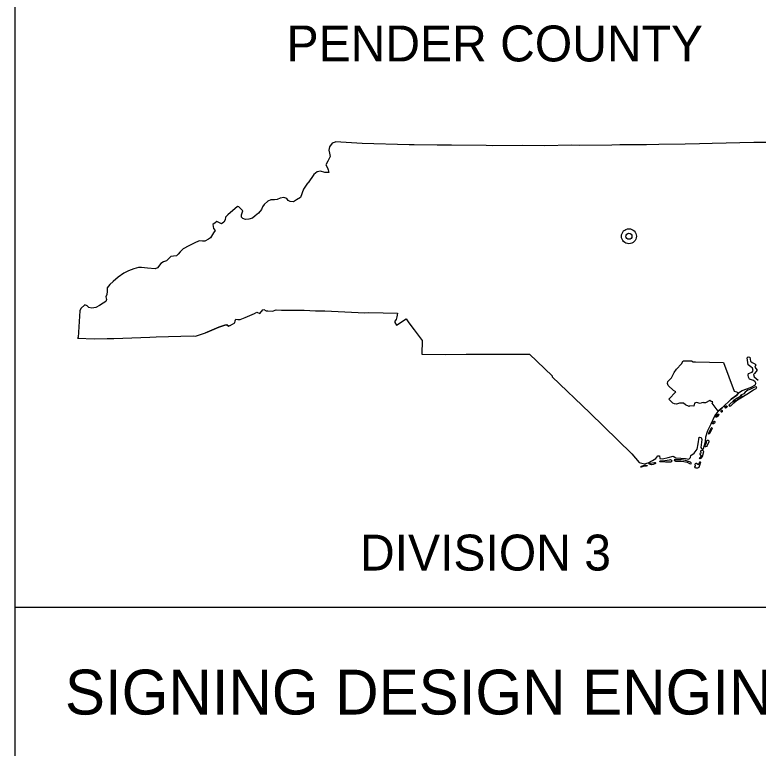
# Model space of a CAD drawing. Extents: x 0 to 1700, y -103 to 1100.
# Drawn here: x 1586.5 to 1660.9, y 952.5 to 1026 of the extents above; entities that cross this region are included whole.
import ezdxf

# ---------------------------------------------------------------- set-up
doc = ezdxf.new("R2010")
doc.units = 0
doc.layers.add('Level 35', color=7, linetype='Continuous')
doc.layers.add('Sheet_Plan_CELL', color=7, linetype='Continuous')

msp = doc.modelspace()

# ---------------------------------------------------------------- linework, layer by layer
at = {"layer": 'Level 35'}
for points in [[(1656.389, 987.241), (1656.214, 987.258), (1656.098, 987.373), (1655.658, 987.124), (1655.494, 987.126), (1655.408, 987.181), (1655.28, 987.149), (1655.129, 987.067), (1654.738, 987.174), (1654.563, 987.11), (1654.494, 986.798), (1654.079, 986.842), (1654.023, 986.757), (1653.657, 986.927), (1653.441, 987.098), (1653.034, 987.113), (1652.743, 987.014), (1652.544, 987.047), (1652.374, 987.09), (1651.982, 987.506), (1652.682, 988.238), (1652.434, 988.388), (1651.902, 988.869), (1651.843, 989.081), (1651.892, 989.289), (1652.242, 989.649), (1652.526, 990.183), (1652.734, 990.513), (1653.238, 991.05), (1653.426, 991.343), (1653.882, 991.36), (1654.238, 991.354), (1654.426, 991.254), (1654.657, 991.242), (1657.46, 991.179), (1658.52, 988.302), (1658.744, 988.249), (1658.971, 988.142), (1658.804, 987.901), (1658.237, 987.487), (1657.322, 986.648), (1656.93, 986.285), (1656.308, 987.093)], [(1659.182, 987.639), (1658.764, 987.382), (1658.503, 987.129), (1658.194, 986.84), (1658.048, 986.803), (1658.012, 986.853), (1658.026, 986.929), (1658.104, 987.013), (1658.425, 987.319), (1658.627, 987.471), (1658.649, 987.504), (1658.722, 987.578), (1658.837, 987.589), (1659.125, 987.787), (1659.209, 987.912), (1659.391, 987.76)], [(1657.603, 986.745), (1657.724, 986.824), (1657.763, 986.829), (1657.813, 986.778), (1657.821, 986.746), (1657.806, 986.698), (1657.77, 986.654), (1657.734, 986.627), (1657.704, 986.618), (1657.67, 986.614), (1657.632, 986.649), (1657.595, 986.698)], [(1657.343, 986.276), (1657.24, 986.221), (1657.201, 986.286), (1657.256, 986.346)]]:
    msp.add_lwpolyline(points, close=True, dxfattribs=at)
for radius in [0.752, 0.3]:
    msp.add_circle((1647.98, 1003.838), radius, dxfattribs=at)
at = {"layer": 'Sheet_Plan_CELL'}
for p, q in [((1586.453, 88.909), (1586.477, 1077.498)), ((1686.502, 966.628), (1586.504, 966.628))]:
    msp.add_line(p, q, dxfattribs=at)
for points in [[(1662.247, 1013.235), (1660.486, 1013.229), (1656.334, 1013.137), (1655.047, 1013.095), (1653.608, 1013.064), (1650.976, 1013.035), (1649.738, 1013.02), (1647.069, 1013.014), (1646.275, 1012.963), (1643.073, 1012.95), (1642.194, 1012.977), (1639.549, 1012.92), (1637.367, 1012.95), (1634.293, 1012.914), (1633.669, 1012.952), (1630.197, 1012.962), (1628.76, 1012.988), (1626.454, 1013.011), (1625.948, 1012.999), (1621.267, 1013.13), (1618.564, 1013.309), (1618.532, 1013.273), (1618.237, 1013.16), (1617.995, 1012.82), (1617.908, 1012.488), (1617.99, 1012.161), (1618.044, 1011.838), (1617.814, 1011.373), (1617.626, 1011.014), (1617.766, 1010.707), (1617.848, 1010.49), (1617.91, 1010.222), (1617.495, 1010.248), (1617.078, 1010.358), (1616.749, 1010.29), (1616.406, 1010.019), (1615.838, 1009.202), (1615.79, 1009.153), (1615.38, 1008.576), (1615.058, 1007.714), (1614.681, 1007.488), (1614.378, 1007.295), (1614.048, 1007.323), (1613.852, 1007.416), (1613.711, 1007.611), (1613.406, 1007.718), (1613.023, 1007.657), (1612.729, 1007.53), (1612.476, 1007.506), (1612.1, 1007.499), (1611.789, 1007.346), (1611.427, 1007.008), (1611.275, 1006.795), (1611.169, 1006.507), (1610.862, 1006.163), (1610.522, 1005.891), (1610.258, 1005.664), (1609.885, 1005.56), (1609.563, 1005.531), (1609.297, 1005.618), (1609.163, 1005.77), (1609.165, 1006.002), (1609.283, 1006.397), (1608.903, 1006.798), (1608.767, 1006.814), (1607.79, 1005.977), (1607.567, 1005.744), (1607.534, 1005.475), (1607.395, 1005.247), (1607.154, 1005.084), (1606.698, 1005.316), (1606.53, 1005.186), (1606.287, 1005.01), (1606.349, 1004.608), (1606.507, 1004.426), (1606.351, 1004.172), (1606.042, 1003.678), (1605.846, 1003.537)], [(1605.846, 1003.537), (1605.504, 1003.333), (1605.269, 1003.333), (1604.928, 1003.373), (1604.405, 1003.148), (1603.876, 1002.883), (1603.301, 1002.569), (1603.003, 1002.264), (1602.811, 1002.041), (1602.639, 1001.871), (1602.332, 1001.838), (1602.081, 1001.812), (1601.878, 1001.604), (1601.66, 1001.385), (1601.33, 1001.273), (1601.089, 1001.096), (1600.751, 1000.673), (1600.505, 1000.565), (1599.741, 1000.623), (1599.143, 1000.69), (1598.828, 1000.697), (1598.361, 1000.586), (1597.844, 1000.385), (1597.364, 1000.153), (1596.808, 999.725), (1596.307, 999.292), (1595.958, 998.991), (1595.701, 998.654), (1595.716, 998.287), (1595.685, 998.006), (1595.562, 997.763), (1595.641, 997.484), (1595.565, 997.29), (1595.302, 997.142), (1594.945, 996.883), (1594.582, 996.692), (1594.165, 996.628), (1593.856, 996.687), (1593.712, 996.878), (1593.474, 996.957), (1593.054, 996.609), (1592.974, 996.375), (1592.785, 993.7), (1592.723, 993.626), (1594.421, 993.556), (1595.706, 993.581), (1596.376, 993.59), (1599.967, 993.722), (1600.626, 993.757), (1604.313, 993.862), (1604.539, 993.808), (1605.565, 994.16), (1605.711, 994.237), (1606.892, 994.732), (1607.49, 994.917), (1607.698, 994.946), (1607.847, 994.82), (1608.034, 994.892), (1608.493, 995.174), (1608.543, 995.357), (1608.578, 995.529), (1608.78, 995.504), (1609.025, 995.488), (1609.545, 995.708), (1610.469, 996.082), (1610.692, 996.217), (1610.992, 996.099), (1611.286, 996.468), (1611.414, 996.506), (1611.63, 996.371), (1611.792, 996.351), (1612.268, 996.319), (1612.641, 996.448), (1613.161, 996.437), (1615.449, 996.418), (1616.581, 996.367), (1617.526, 996.353), (1621.51, 996.177), (1621.911, 996.204), (1624.797, 996.121), (1624.732, 995.765), (1624.654, 995.505), (1624.52, 995.334), (1624.527, 995.184), (1624.695, 994.918), (1625.648, 995.543), (1625.922, 995.153), (1626.453, 994.457), (1627.268, 993.37), (1627.225, 992.026), (1629.572, 991.99), (1631.683, 992.022), (1635.705, 992.008), (1637.857, 992.021), (1638.02, 992.009), (1640.276, 989.84), (1640.29, 989.757), (1644.059, 986.135), (1648.258, 982.019), (1649.019, 981.143)], [(1608.034, 994.892), (1607.847, 994.82), (1607.698, 994.946), (1607.49, 994.917), (1606.892, 994.732), (1605.711, 994.237), (1605.565, 994.16)], [(1649.019, 981.143), (1649.542, 981.03), (1649.899, 981.132), (1650.33, 981.355), (1650.662, 981.555), (1650.869, 981.815), (1651.045, 981.813), (1651.084, 981.565), (1651.346, 981.508), (1651.925, 981.639), (1652.409, 981.772), (1652.682, 981.619), (1653.189, 981.573), (1653.662, 981.56), (1653.989, 981.491), (1654.166, 981.649), (1654.2, 981.844), (1654.527, 982.084), (1654.818, 982.504), (1654.934, 983.008), (1655.003, 983.709), (1655.042, 983.702), (1655.212, 983.659), (1655.27, 983.448), (1655.2, 982.667), (1655.243, 982.565), (1655.331, 982.502), (1655.42, 982.503), (1655.459, 982.559), (1655.51, 982.802), (1655.641, 983.236), (1655.671, 983.715), (1655.878, 984.352), (1656.214, 985.021), (1656.601, 985.816), (1656.843, 986.179), (1656.93, 986.285), (1657.322, 986.648), (1658.237, 987.487), (1658.804, 987.901), (1658.971, 988.142), (1659.328, 988.377), (1660.149, 988.678), (1660.662, 988.939), (1660.707, 989.107), (1660.638, 989.254), (1660.453, 989.368), (1660.053, 989.506), (1659.951, 989.7), (1659.933, 989.906), (1659.978, 990.074), (1660.317, 990.204), (1660.414, 990.363), (1660.375, 990.6), (1660.181, 990.743), (1660.06, 990.832), (1659.933, 990.962), (1659.821, 991.633), (1659.925, 991.75), (1660.085, 991.722), (1660.177, 991.326), (1660.313, 991.166), (1660.61, 991.06), (1660.684, 990.938), (1660.585, 990.698), (1660.845, 990.395), (1660.568, 990.078), (1660.465, 989.961), (1660.537, 989.759), (1660.939, 989.403)], [(1658.425, 987.319), (1658.104, 987.013), (1658.026, 986.929), (1658.012, 986.853), (1658.048, 986.803), (1658.194, 986.84), (1658.503, 987.129), (1658.764, 987.382), (1659.182, 987.639), (1659.81, 988.002), (1660.452, 988.441), (1660.678, 988.533), (1660.735, 988.589), (1660.789, 988.708), (1660.668, 988.754), (1660.5, 988.664), (1660.084, 988.487), (1659.896, 988.404), (1659.636, 988.204), (1659.497, 988.051), (1659.209, 987.912), (1659.125, 987.787), (1658.837, 987.589), (1658.722, 987.578), (1658.649, 987.504), (1658.627, 987.471), (1658.439, 987.329)], [(1657.603, 986.745), (1657.724, 986.824), (1657.763, 986.829), (1657.786, 986.812), (1657.813, 986.778), (1657.821, 986.746), (1657.806, 986.698), (1657.77, 986.654), (1657.734, 986.627), (1657.704, 986.618), (1657.67, 986.614), (1657.632, 986.649), (1657.595, 986.698), (1657.589, 986.725), (1657.603, 986.745)], [(1657.256, 986.346), (1657.201, 986.286), (1657.196, 986.253), (1657.211, 986.227), (1657.24, 986.221), (1657.287, 986.234), (1657.343, 986.276), (1657.364, 986.302), (1657.357, 986.326), (1657.31, 986.368), (1657.294, 986.374), (1657.272, 986.365), (1657.26, 986.351)], [(1656.718, 985.751), (1656.792, 985.875), (1656.87, 985.959), (1656.917, 985.994), (1656.953, 985.997), (1656.983, 985.97), (1657.001, 985.932), (1656.962, 985.888), (1656.895, 985.798), (1656.836, 985.738), (1656.747, 985.691), (1656.721, 985.69), (1656.703, 985.703), (1656.695, 985.718), (1656.718, 985.751)], [(1655.958, 984.106), (1655.949, 984.019), (1655.964, 984.011), (1655.999, 984.017), (1656.049, 984.045), (1656.079, 984.083), (1656.336, 984.515), (1656.345, 984.572), (1656.335, 984.602), (1656.297, 984.628), (1656.26, 984.628), (1656.206, 984.597), (1656.174, 984.557), (1655.975, 984.167), (1655.957, 984.107)], [(1656.353, 985.052), (1656.394, 985.142), (1656.446, 985.217), (1656.495, 985.257), (1656.554, 985.288), (1656.588, 985.279), (1656.601, 985.248), (1656.579, 985.178), (1656.541, 985.093), (1656.5, 985.053), (1656.445, 985.017), (1656.373, 985.024), (1656.355, 985.032), (1656.351, 985.059)], [(1655.749, 983.114), (1655.755, 983.237), (1655.764, 983.328), (1655.806, 983.374), (1655.866, 983.4), (1655.925, 983.383), (1655.983, 983.338), (1655.982, 983.225), (1655.828, 982.86), (1655.741, 982.755), (1655.663, 982.717), (1655.615, 982.739), (1655.609, 982.799), (1655.67, 982.931), (1655.751, 983.121)], [(1655.489, 982.261), (1655.415, 982.333), (1655.241, 982.358), (1655.183, 982.322), (1655.143, 982.289), (1655.154, 982.254), (1655.214, 982.183)], [(1655.214, 982.183), (1655.164, 982.1), (1655.081, 982.042), (1655.069, 982.017), (1655.074, 981.984), (1655.163, 981.891), (1655.21, 981.852), (1655.229, 981.837), (1655.228, 981.787), (1655.05, 981.601), (1655.035, 981.574), (1655.088, 981.532), (1655.124, 981.544), (1655.206, 981.595), (1655.342, 981.755), (1655.489, 982.261)], [(1649.161, 980.727), (1649.249, 980.786), (1649.426, 980.858), (1649.546, 980.889), (1649.623, 980.895), (1649.689, 980.887), (1649.763, 980.867), (1649.797, 980.852), (1649.806, 980.833), (1649.8, 980.819), (1649.715, 980.773), (1649.695, 980.78), (1649.677, 980.795), (1649.598, 980.779), (1649.436, 980.748), (1649.298, 980.711), (1649.217, 980.69), (1649.187, 980.687), (1649.169, 980.705), (1649.161, 980.727)], [(1650.1, 981.086), (1650.53, 981.142), (1650.616, 981.141), (1650.657, 981.126), (1650.642, 981.06), (1650.583, 981.012), (1650.399, 980.939), (1650.259, 980.919), (1650.036, 980.975), (1649.978, 981.004), (1650.015, 981.052), (1650.11, 981.094)], [(1651.147, 981.322), (1651.568, 981.355), (1652.033, 981.434), (1652.149, 981.441), (1652.245, 981.389), (1652.299, 981.324), (1652.287, 981.281), (1652.177, 981.201), (1652.094, 981.178), (1651.643, 981.202), (1651.318, 981.211), (1651.184, 981.212), (1651.111, 981.233), (1651.083, 981.258), (1651.083, 981.276), (1651.087, 981.291), (1651.146, 981.316)], [(1652.529, 981.392), (1652.692, 981.288), (1652.863, 981.295), (1653.185, 981.284), (1653.478, 981.252), (1653.807, 981.181), (1654.05, 981.053), (1654.152, 981.009), (1654.242, 981.05), (1654.221, 981.135), (1654.15, 981.185), (1653.659, 981.35), (1653.264, 981.426), (1652.619, 981.433), (1652.529, 981.422), (1652.534, 981.392)], [(1654.735, 981.089), (1654.898, 980.975), (1654.939, 980.961), (1654.998, 981.032), (1655.076, 981.224), (1655.122, 981.245), (1655.158, 981.185), (1655.007, 980.745), (1654.973, 980.638), (1654.843, 980.576), (1654.732, 980.57), (1654.631, 980.609), (1654.599, 980.709), (1654.638, 980.831), (1654.626, 981.002), (1654.64, 981.037), (1654.725, 981.094), (1654.751, 981.089)]]:
    msp.add_lwpolyline(points, dxfattribs=at)

# ---------------------------------------------------------------- texts
for s, height, p in [('PENDER COUNTY', 3.6, (1613.676, 1021.37)), ('DIVISION 3', 3.6, (1621.035, 970.32)), ('SIGNING DESIGN ENGINEER', 4.5, (1591.469, 955.88))]:
    msp.add_text(s, height=height, rotation=0, dxfattribs=at).set_placement(p)

doc.saveas('drawing.dxf')
